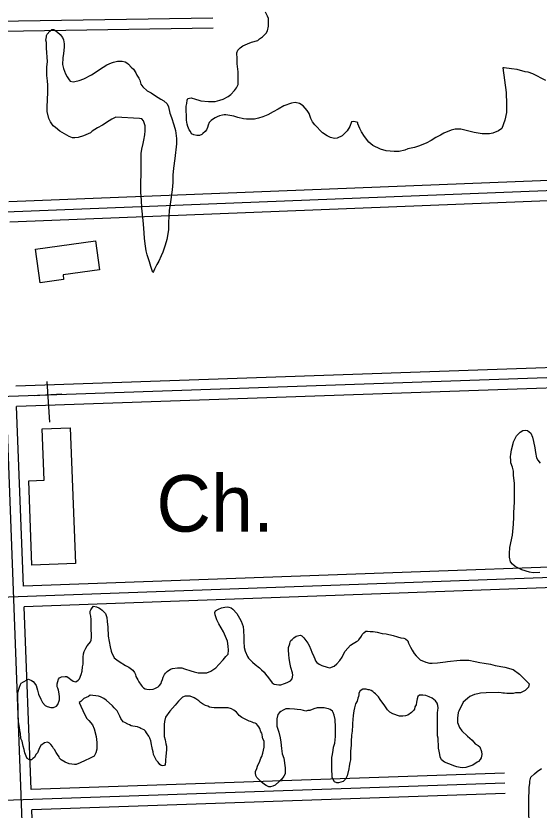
# Model space of a CAD drawing. Extents: x 3313442 to 3351311, y 721974 to 747360.
# Drawn here: x 3329367 to 3330135, y 735697 to 736863 of the extents above; entities that cross this region are included whole.
import ezdxf

# ---------------------------------------------------------------- set-up
doc = ezdxf.new("R2010")
doc.units = 0
for name, color, linetype in [('V-BLDG-OTLN', 7, 'Continuous'), ('V-ROAD-CNTR', 7, 'Continuous'), ('V-SITE-OTLN', 7, 'Continuous'), ('V-SITE-OTLN-IDEN', 7, 'Continuous'), ('V-SITE-VEGE', 7, 'Continuous')]:
    doc.layers.add(name, color=color, linetype=linetype)

msp = doc.modelspace()

# ---------------------------------------------------------------- linework, layer by layer
at = {"layer": 'V-BLDG-OTLN'}
for points in [[(3329395.7, 736520.5), (3329483.8, 736532.8), (3329489.7, 736490.2), (3329436, 736482.7), (3329436.9, 736475.9), (3329402.6, 736471.1)], [(3329390.3, 736056.5), (3329385.6, 736180.3), (3329408.2, 736181.1), (3329405.3, 736256.6), (3329446.7, 736258.2), (3329454.3, 736058.9)]]:
    msp.add_lwpolyline(points, close=True, dxfattribs=at)
at = {"layer": 'V-ROAD-CNTR'}
for points in [[(3329053, 736850.7), (3329656, 736860.3)], [(3329385.8, 735418.9), (3329331.6, 736855.2)], [(3329347.2, 736840.4), (3329656.3, 736845.3)], [(3330731.3, 736644.4), (3329356.6, 736589.9)], [(3330826.8, 736633.2), (3329004.7, 736561)], [(3330827.4, 736618.2), (3329357.7, 736560)], [(3330921, 736373.3), (3329366.8, 736319.4)], [(3330921.6, 736358.4), (3328961.1, 736290.3)], [(3330922.1, 736343.4), (3329367.9, 736289.4)], [(3329377.9, 736025.4), (3329367.9, 736289.4)], [(3331148.5, 736086.5), (3330760.3, 736075.5), (3329377.9, 736025.4)], [(3331148.9, 736071.5), (3330760.7, 736060.5), (3328937.8, 735994.4), (3327458.7, 735955.1), (3325793.6, 735902.5)], [(3330975, 736051.6), (3330761.2, 736045.5), (3329379, 735995.4)], [(3329389.2, 735727.3), (3329379, 735995.4)], [(3330083.8, 735751.3), (3329389.2, 735727.3)], [(3330084.3, 735736.3), (3328967.1, 735697.7)], [(3330084.9, 735721.3), (3329390.3, 735697.3)], [(3329400.2, 735434.5), (3329390.3, 735697.3)]]:
    msp.add_lwpolyline(points, dxfattribs=at)
at = {"layer": 'V-SITE-OTLN'}
for p, q in [((3329416.8, 736266.4), (3329412.9, 736326.3)), ((3329434.1, 736307.6), (3329394.2, 736305.1))]:
    msp.add_line(p, q, dxfattribs=at)
at = {"layer": 'V-SITE-VEGE'}
for points in [[(3329794.3, 736724.1), (3329788.4, 736730.9), (3329783.2, 736734.3), (3329776.6, 736736), (3329771.5, 736734.9), (3329760.1, 736730.7), (3329751.9, 736726.1), (3329744.4, 736722.3), (3329736.8, 736717.7), (3329729.3, 736714.6), (3329723.1, 736712.8), (3329716.9, 736711.4), (3329705.2, 736711.3), (3329700.7, 736711.9), (3329692.7, 736713.9), (3329686.9, 736716), (3329675.1, 736717.6), (3329672.4, 736717.6), (3329670.3, 736717.2), (3329665.5, 736716.1), (3329662.1, 736714.7), (3329659.3, 736713.3), (3329655.2, 736710.9), (3329653.5, 736709.2), (3329650.4, 736706.4), (3329649.1, 736702.6), (3329648.1, 736699.1), (3329646.7, 736695.7), (3329644.7, 736693.2), (3329641.2, 736690.1), (3329639.5, 736688.7), (3329636.4, 736687.6), (3329632.3, 736687.6), (3329628.2, 736688.6), (3329624.7, 736690), (3329623, 736693.1), (3329621.2, 736695.8), (3329619.4, 736700.6), (3329618.4, 736704), (3329617, 736709.9), (3329616.8, 736730.6), (3329617.8, 736734.4), (3329618.1, 736739.5), (3329619.1, 736741.6), (3329624.3, 736742.7), (3329630.2, 736740.7), (3329635.3, 736739.3), (3329638.4, 736738.3), (3329649.5, 736737.4), (3329659.1, 736737.5), (3329666.3, 736739.2), (3329671.2, 736740.7), (3329678.4, 736744.5), (3329682.5, 736747.6), (3329687.6, 736753.5), (3329690.7, 736757.3), (3329693, 736762.5), (3329693.3, 736772.9), (3329693.2, 736780.8), (3329691.8, 736792.5), (3329691.4, 736800.1), (3329691.3, 736809), (3329692.6, 736812.5), (3329696.1, 736816.3), (3329699.8, 736818.8), (3329706.7, 736821.9), (3329712.5, 736824.4), (3329721.8, 736826.9), (3329724.6, 736829.3), (3329729, 736832.1), (3329730.4, 736833.8), (3329734.1, 736837.6), (3329736.2, 736841.1), (3329737.5, 736848), (3329737.4, 736859), (3329736.3, 736862.8), (3329733.2, 736868.7)], [(3329568.8, 736487.9), (3329567.8, 736486.2), (3329564.9, 736494.8), (3329562.8, 736501.7), (3329559.3, 736512), (3329557.8, 736518.2), (3329556.4, 736528.5), (3329555.6, 736536.4), (3329554.8, 736551.2), (3329553.7, 736562.6), (3329551.5, 736580.5), (3329551.1, 736592.2), (3329550.3, 736603.6), (3329550.1, 736621.1), (3329550.8, 736627.7), (3329550.6, 736651.8), (3329550.8, 736661.1), (3329551.8, 736667.3), (3329553.8, 736675.6), (3329554.5, 736680.4), (3329556.1, 736688.4), (3329556.8, 736694.2), (3329556.7, 736701.5), (3329553.9, 736708.7), (3329551.8, 736711.8), (3329548, 736712.4), (3329513.5, 736714.2), (3329507.7, 736711.4), (3329503.6, 736709), (3329494, 736702.4), (3329486.8, 736698.5), (3329478.9, 736693.6), (3329476.2, 736691.5), (3329465.9, 736687), (3329458, 736684.5), (3329453.1, 736684.1), (3329449.7, 736684.1), (3329444.9, 736685.8), (3329431.3, 736693.6), (3329424.8, 736699), (3329421.3, 736701.8), (3329417.8, 736707.3), (3329415.3, 736712.1), (3329412.9, 736722.4), (3329412.8, 736729.6), (3329413.7, 736750.6), (3329413.6, 736761.3), (3329413.2, 736767.5), (3329412.4, 736775.4), (3329412.3, 736787.5), (3329413, 736795.8), (3329411.8, 736815.4), (3329411.7, 736823.7), (3329411, 736827.5), (3329411.6, 736832.3), (3329411.6, 736834.4), (3329412.6, 736836.1), (3329416.7, 736840.6), (3329419.8, 736843), (3329422.6, 736843.1), (3329428.1, 736839.3), (3329431.9, 736835.9), (3329435.4, 736831.1), (3329436.8, 736828), (3329437.9, 736821.8), (3329437.9, 736817), (3329436.6, 736807.7), (3329435.6, 736801.5), (3329435.4, 736791.5), (3329436.5, 736785.6), (3329439.6, 736778.1), (3329442.1, 736773.3), (3329444.9, 736769.2), (3329446.6, 736767.4), (3329450.7, 736766.4), (3329453.2, 736766.5), (3329459.7, 736767.9), (3329466.6, 736770.4), (3329477.9, 736776.3), (3329494.7, 736787.8), (3329500.2, 736791.3), (3329507, 736794.1), (3329510.1, 736795.2), (3329516, 736796.6), (3329522.9, 736796.7), (3329527.4, 736795.3), (3329529.8, 736794), (3329532.2, 736791.9), (3329536, 736787.5), (3329539.2, 736784.7), (3329542.7, 736779.2), (3329544.4, 736775.8), (3329547.2, 736771.7), (3329548.6, 736768.6), (3329550.4, 736762.8), (3329553.2, 736759), (3329559.4, 736753.2), (3329565.3, 736749.8), (3329571.5, 736745.4), (3329575.7, 736743), (3329579.5, 736740.6)], [(3330144.8, 736767.9), (3330125.7, 736778.1), (3330118.8, 736780.4), (3330114.3, 736781.1), (3330102.6, 736784.1), (3330094.3, 736785.4), (3330083.6, 736786.7), (3330081.6, 736786.7), (3330086.3, 736750.5), (3330086.8, 736733.3), (3330086.9, 736721.2), (3330084.6, 736709.9), (3330079.9, 736697.8), (3330075.4, 736694.3), (3330066.8, 736690.8), (3330062, 736690), (3330051.3, 736689.9), (3330039.6, 736691.6), (3330019.9, 736696.9), (3330011.6, 736696.9), (3330005.8, 736695.1), (3329995.1, 736690.9), (3329990, 736687.7), (3329983.1, 736684.2), (3329976.3, 736680), (3329969.1, 736676.2), (3329957.7, 736671.6), (3329951.9, 736669.9), (3329942.3, 736667.7), (3329937.5, 736665.6), (3329929.2, 736663.8), (3329922, 736663.8), (3329910.2, 736665), (3329901.9, 736667.4), (3329890.5, 736672.8), (3329884.6, 736677.6), (3329878.4, 736686.1), (3329874.2, 736693), (3329871.4, 736697.8), (3329868.9, 736704.7), (3329868.9, 736706.7), (3329863, 736708.1), (3329859.2, 736707.4), (3329856.9, 736700.8), (3329852.8, 736694.2), (3329845.6, 736686.9), (3329838.4, 736683.4), (3329834.6, 736683), (3329828.8, 736684.4), (3329823.6, 736686.7), (3329817, 736691.5), (3329805.5, 736702.8), (3329802, 736707.6), (3329799.6, 736712.4), (3329797.1, 736719.6), (3329794.3, 736724.1)], [(3329579.5, 736740.6), (3329584, 736738.2), (3329588.9, 736733.8), (3329590.6, 736729.7), (3329592.8, 736720.4), (3329595.2, 736713.8), (3329598.8, 736702.8), (3329600.9, 736694.9), (3329602.4, 736682.9), (3329602.4, 736675), (3329600.2, 736653.6), (3329598.2, 736639.4), (3329597.3, 736629.1), (3329597, 736618.4), (3329596.1, 736607.7), (3329593.5, 736590.1), (3329591.8, 736577.4), (3329590.6, 736559.8), (3329590.7, 736549.1), (3329588.4, 736534.6), (3329586, 736526.3), (3329582.3, 736515.9), (3329580, 736510.8), (3329576.6, 736502.8), (3329573.5, 736498), (3329570.1, 736491), (3329568.8, 736487.9)], [(3330135.8, 736045.5), (3330126.1, 736045.4), (3330120.9, 736046.1), (3330109.2, 736049.8), (3330099.5, 736054.5), (3330095.7, 736058), (3330092.6, 736061.4), (3330091.1, 736068.3), (3330091.1, 736073.4), (3330091.7, 736082.4), (3330095.7, 736100.3), (3330097.3, 736116.9), (3330097.9, 736126.9), (3330097.8, 736133.4), (3330098.7, 736149.6), (3330098.5, 736176.9), (3330097.4, 736188.2), (3330097.4, 736194.4), (3330095.9, 736200.3), (3330093.5, 736206.8), (3330093.1, 736209.9), (3330093, 736215.8), (3330093.4, 736219.2), (3330094.3, 736225.8), (3330096.7, 736235.1), (3330097, 736237.8), (3330099.4, 736242.7), (3330101.8, 736246.2), (3330106.9, 736251.7), (3330110.7, 736254.2), (3330115.1, 736254.5), (3330117.5, 736254.2), (3330120.3, 736252.5), (3330122.7, 736250.1), (3330125.2, 736244.3), (3330126.3, 736238.1), (3330128.4, 736228.8), (3330129.5, 736221.9), (3330131, 736214.3), (3330133.1, 736210.9), (3330136.2, 736206.1)], [(3329453, 735764), (3329445, 735765), (3329439.1, 735767), (3329433.3, 735770.4), (3329430.8, 735773.1), (3329430.1, 735775.2), (3329428, 735778.6), (3329425.9, 735781.4), (3329423.5, 735785.8), (3329422.1, 735787.5), (3329420.7, 735790.3), (3329418.3, 735793.4), (3329416.2, 735795.1), (3329413.1, 735796.4), (3329408.9, 735795.4), (3329403.5, 735791.5), (3329401.4, 735788.1), (3329400.7, 735786), (3329398.4, 735781.1), (3329396.3, 735778.4), (3329393.9, 735774.2), (3329391.5, 735772.8), (3329389.5, 735770.7), (3329386.7, 735770.4), (3329383.3, 735772.8), (3329381.9, 735775.8), (3329380.1, 735781), (3329379, 735785.8), (3329377.6, 735790.6), (3329375.8, 735798.2), (3329374.1, 735802), (3329373.7, 735809.2), (3329372.6, 735813.7), (3329372.2, 735818.1), (3329370.4, 735826.8), (3329370, 735838.1), (3329369.7, 735869.5), (3329372.1, 735877.4), (3329373.4, 735881.2), (3329374.5, 735883.3), (3329377.9, 735885.4), (3329383.4, 735888.2), (3329385.1, 735889.2), (3329389.9, 735887.2), (3329392.4, 735885.9), (3329395.5, 735881.4), (3329396.5, 735879.7), (3329398.3, 735872.8), (3329400.1, 735867.3), (3329403.6, 735859.8), (3329406, 735855), (3329409.9, 735850.5), (3329412.6, 735849.1), (3329418.2, 735847.5), (3329422, 735847.5), (3329426.4, 735849.3), (3329428.5, 735852), (3329430.8, 735858.9), (3329430.8, 735863.8), (3329429.7, 735870.6), (3329429.3, 735872.7), (3329428.6, 735875.8), (3329427.6, 735877.9), (3329427.5, 735882.3), (3329428.2, 735885.8), (3329429.5, 735889.3), (3329430.9, 735891), (3329434, 735892.7), (3329439.2, 735893.1), (3329441.6, 735892.8), (3329445, 735890.8), (3329447.5, 735888.7), (3329450.9, 735886.3), (3329454.7, 735885.3), (3329458.2, 735887.4), (3329460.2, 735889.8), (3329462.6, 735895.7), (3329463.9, 735900.6), (3329464.6, 735907.1), (3329465.6, 735911.3), (3329465.5, 735921.2), (3329466.1, 735926.1), (3329467.1, 735929.5), (3329469.5, 735934.4), (3329471.5, 735937.8), (3329474.3, 735941.3), (3329476.3, 735943.7), (3329477.3, 735946.5), (3329477.6, 735951), (3329477.5, 735966.1), (3329477.1, 735976.8), (3329476.7, 735981.6), (3329476, 735985.4), (3329476, 735988.9), (3329476.6, 735990.9), (3329479, 735993.7), (3329480.7, 735996.2), (3329484.9, 735995.1), (3329488.7, 735993.8), (3329491.1, 735992.4), (3329493.5, 735990.4)], [(3329493.5, 735990.4), (3329497, 735987), (3329498.4, 735985.3), (3329500.5, 735979.8), (3329500.9, 735973.9), (3329501.6, 735965.3), (3329502.4, 735952.2), (3329505.3, 735936.4), (3329506.8, 735930.2), (3329507.8, 735927.4), (3329510.3, 735923), (3329511.3, 735920.6), (3329515.1, 735917.5), (3329518.6, 735915.1), (3329527.9, 735909.3), (3329532.8, 735906.6), (3329538.7, 735902.2), (3329541.1, 735898.8), (3329542.2, 735896), (3329542.9, 735892.9), (3329545.7, 735888.1), (3329547.1, 735885), (3329550.6, 735880.2), (3329552, 735878.5), (3329554, 735876.5), (3329556.8, 735875.1), (3329558.9, 735874.4), (3329563, 735874.1), (3329568.2, 735874.5), (3329570.9, 735875.6), (3329575.4, 735878), (3329577.1, 735879.4), (3329579.8, 735882.9), (3329580.5, 735885), (3329582.2, 735888.8), (3329582.9, 735891.9), (3329584.9, 735895.7), (3329586.3, 735897.8), (3329588.7, 735900.5), (3329593.8, 735903.7), (3329596.9, 735904.7), (3329603.8, 735905.5), (3329610.3, 735905.5), (3329614.1, 735904.2), (3329623.8, 735901.5), (3329628.3, 735899.8), (3329634.2, 735898.5), (3329638, 735898.2), (3329642.8, 735898.2), (3329646.9, 735898.6), (3329652.8, 735900.7), (3329654.5, 735901.7), (3329660.3, 735905.9), (3329664.7, 735910.4), (3329670.9, 735917.7), (3329675, 735922.2), (3329678.4, 735925.7), (3329678.7, 735931.9), (3329678.6, 735937.4), (3329677.2, 735944.7), (3329675.8, 735948.4), (3329671.6, 735958.4), (3329664.6, 735970.4), (3329661.8, 735976.2), (3329659.3, 735983.5), (3329658.6, 735986.9), (3329659.6, 735989.3), (3329664.1, 735991.8), (3329668.5, 735993.9), (3329673.7, 735994.9), (3329676.8, 735995.3), (3329679.6, 735995), (3329683, 735993.6), (3329685.1, 735991.9), (3329691, 735985.4), (3329694.9, 735978.9), (3329697.3, 735974.1), (3329700.5, 735966.2), (3329700.9, 735960.4), (3329701.3, 735950.7), (3329701.3, 735944.5), (3329702.1, 735935.6), (3329703.2, 735930.4), (3329706.7, 735922.5), (3329708.1, 735920.1), (3329714, 735913.9), (3329717.8, 735910.5)], [(3329717.8, 735910.5), (3329724.4, 735905.8), (3329727.2, 735902.7), (3329731, 735899.3), (3329733.4, 735896.5), (3329737.6, 735891), (3329742.8, 735883.8), (3329746, 735881.8), (3329752.9, 735880.8), (3329755.6, 735880.8), (3329761.1, 735882.6), (3329765.2, 735884.4), (3329769.7, 735886.8), (3329772.1, 735889.6), (3329773.4, 735894.8), (3329773, 735898.6), (3329770.6, 735906.1), (3329769.5, 735911.3), (3329768.1, 735919.2), (3329767.3, 735925.1), (3329766.9, 735931.9), (3329766.9, 735935.7), (3329768.9, 735940.9), (3329769.2, 735944), (3329770.6, 735946.1), (3329772.3, 735947.5), (3329774.7, 735949.9), (3329778.1, 735952), (3329781.9, 735953.4), (3329784.7, 735953.8), (3329786.4, 735952.8), (3329789.5, 735950), (3329795.1, 735941.8), (3329797.2, 735938.4), (3329799.6, 735932.5), (3329801.1, 735928.8), (3329803.9, 735922.2), (3329805.6, 735918.8), (3329806.7, 735916.1), (3329808.4, 735913.7), (3329811.9, 735911.3), (3329815.7, 735909.2), (3329823.6, 735906.6), (3329827.4, 735905.9), (3329834, 735908), (3329838.1, 735911.5), (3329842.5, 735916.7), (3329845.6, 735921.2), (3329848.3, 735926.7), (3329850.3, 735930.2), (3329857.8, 735938.9), (3329861.9, 735941.7), (3329866.7, 735944.5), (3329868.8, 735945.2), (3329870.2, 735946.9), (3329873.9, 735952.1), (3329875.3, 735954.5), (3329877.7, 735957), (3329880.4, 735959.4), (3329882.8, 735959.4), (3329886.6, 735959.1), (3329891.1, 735959.1), (3329893.9, 735958.8), (3329897.3, 735958.1), (3329904.6, 735956.1), (3329910.1, 735955.5), (3329920.8, 735953.2), (3329926.7, 735951.1), (3329931.8, 735949.8), (3329936, 735949.2), (3329938.7, 735948.1), (3329941.9, 735945.4), (3329943.3, 735942), (3329946.1, 735936.1), (3329948.5, 735931.7), (3329951.3, 735926.9), (3329954.1, 735923.5), (3329957.6, 735920), (3329960.4, 735917.6), (3329968.3, 735913.9), (3329973.8, 735912.6), (3329978, 735912.6), (3329985.5, 735913), (3329997.6, 735914.5), (3330000.3, 735915.2), (3330004.5, 735915.6), (3330013.8, 735916.7), (3330018.9, 735917.1), (3330028.2, 735917.2), (3330031.7, 735916.8), (3330041, 735914.8), (3330047.9, 735913.5), (3330054.1, 735912.5), (3330063.4, 735910.9), (3330070.4, 735909.2), (3330084.5, 735906.9), (3330096.9, 735903.2), (3330105.9, 735896.4), (3330111.9, 735890.6), (3330115.7, 735886.5), (3330120.2, 735882.1)], [(3330120.2, 735882.1), (3330119.2, 735877.2), (3330114.4, 735872.4), (3330107.5, 735869.2), (3330105.5, 735868.8), (3330100.3, 735868.8), (3330096.9, 735868.1), (3330087.6, 735868), (3330083.8, 735868.7), (3330081.7, 735868.7), (3330079.3, 735869), (3330075.5, 735869.3), (3330056.9, 735869.1), (3330048.6, 735868.4), (3330044.8, 735867.7), (3330040, 735866.6), (3330033.2, 735863.8), (3330029.7, 735860.7), (3330023.2, 735855.4), (3330016.8, 735842.3), (3330016.1, 735839.9), (3330015.1, 735831.6), (3330015.2, 735825.7), (3330017.7, 735818.2), (3330021.2, 735813.4), (3330029.5, 735805.2), (3330036.4, 735799.4), (3330041, 735794.2), (3330045.4, 735791.9), (3330047.9, 735789.5), (3330050.3, 735782.9), (3330050.7, 735778.5), (3330049.7, 735773.6), (3330048.4, 735771.2), (3330045.6, 735768.4), (3330043.9, 735767.4), (3330037.4, 735762.8), (3330032.9, 735761.1), (3330027.4, 735759.3), (3330022.3, 735758.9), (3330018.8, 735759.3), (3330014, 735760.2), (3330010.9, 735761.3), (3330002.2, 735764.6), (3329995.7, 735767.3), (3329991.5, 735770.7), (3329989.4, 735775.2), (3329989, 735778.7), (3329988.3, 735783.5), (3329987.2, 735787.9), (3329986.9, 735793.8), (3329986.8, 735797.6), (3329986.4, 735802.4), (3329985.7, 735805.9), (3329985.4, 735840), (3329986.1, 735843.1), (3329986.4, 735847.2), (3329986.1, 735850.3), (3329985.3, 735853.7), (3329982.9, 735857.2), (3329977.7, 735861.3), (3329973.5, 735863), (3329968.7, 735865.3), (3329963.9, 735865.6), (3329959, 735865.6), (3329957, 735863.5), (3329955.6, 735860.1), (3329955, 735855.2), (3329954.3, 735851.4), (3329952.6, 735848.3), (3329952, 735845.2), (3329951, 735843.5), (3329947.5, 735840), (3329942.1, 735836.2), (3329938.6, 735835.1), (3329934.8, 735834.7), (3329930, 735834.7), (3329920.3, 735838.4), (3329915.8, 735840.8), (3329912.4, 735843.9), (3329908.5, 735849.7), (3329901.6, 735859.3), (3329899.1, 735863), (3329894.6, 735867.5), (3329892.5, 735868.9), (3329890.8, 735870.9), (3329888.4, 735872.3), (3329885.9, 735873.3), (3329883.9, 735873.6), (3329881.1, 735874.3), (3329875.9, 735874.2), (3329872.2, 735872.1), (3329870.1, 735868.3), (3329870.1, 735866.3), (3329869.8, 735863.5), (3329868.8, 735861.1), (3329867.5, 735856.6), (3329865.4, 735852.8), (3329863.7, 735846.9), (3329862.7, 735842.8), (3329861.8, 735835.5)], [(3329713.7, 735826.1), (3329711.2, 735827.1), (3329709.2, 735827.4), (3329706.4, 735829.1), (3329702.3, 735830.8), (3329698.4, 735832.8), (3329694.6, 735835.6), (3329693.2, 735837.6), (3329690.8, 735840.7), (3329686.6, 735843.4), (3329683.2, 735845.5), (3329678.3, 735846.8), (3329674.6, 735846.8), (3329669, 735847.1), (3329658, 735847), (3329653.9, 735847.6), (3329651.1, 735848), (3329648.3, 735849.3), (3329645.2, 735850.3), (3329640.7, 735852.7), (3329638, 735854.7), (3329635.5, 735857.1), (3329631, 735860.2), (3329628.6, 735861.6), (3329622.4, 735864.3), (3329615.5, 735864.2), (3329611.4, 735862.5), (3329609, 735860.4), (3329605.6, 735856.9), (3329600.4, 735851), (3329592.6, 735842.3), (3329586.4, 735833.3), (3329585.1, 735827.1), (3329584.5, 735822.6), (3329584.6, 735804.7), (3329585.7, 735800.2), (3329586.8, 735794), (3329587.8, 735790.6), (3329587.9, 735785.8), (3329586.9, 735775.4), (3329586.3, 735770.6), (3329586.3, 735768.2), (3329586, 735764), (3329584.9, 735762.3), (3329582.5, 735761.6), (3329580.1, 735762.3), (3329578, 735763.6), (3329575.6, 735767.1), (3329573.2, 735769.8), (3329570.4, 735775.3), (3329569, 735778.7), (3329568.2, 735782.5), (3329567.2, 735785.9), (3329566.5, 735790.8), (3329565.7, 735792.8), (3329565.4, 735796.3), (3329564.7, 735798.7), (3329563.3, 735802.5), (3329561.9, 735805.5), (3329558.7, 735810.3), (3329557, 735812.7), (3329554.9, 735814.5), (3329550.4, 735816.5), (3329548.7, 735817.5), (3329545.2, 735818.9), (3329538.3, 735820.2), (3329535.9, 735820.8), (3329533.5, 735821.9), (3329531, 735823.2), (3329526.9, 735825.3), (3329524.5, 735826.6), (3329521, 735831.4), (3329519.6, 735834.8), (3329515.7, 735842.4), (3329511.2, 735846.8), (3329508.8, 735849.9), (3329499.1, 735858.1), (3329495.9, 735860.5), (3329491.1, 735863.2), (3329488.3, 735864.2), (3329475.9, 735865.5), (3329473.5, 735863.8), (3329470.1, 735862.4), (3329466.3, 735860.6), (3329461.9, 735856.4), (3329459.5, 735854.7), (3329467.5, 735837.9), (3329471, 735831.3), (3329473.8, 735828.6), (3329479.4, 735822.1), (3329481.8, 735816.3), (3329484.7, 735804.9), (3329485.4, 735796.3), (3329485.5, 735786.3), (3329484.2, 735780.8), (3329481.5, 735776), (3329474.9, 735772.5), (3329468.4, 735769.6), (3329461.2, 735766.1), (3329455.4, 735764), (3329453, 735764)], [(3329861.8, 735835.5), (3329860.8, 735823.8), (3329860.8, 735821.4), (3329860.6, 735812.8), (3329859.6, 735806.9), (3329859, 735797.6), (3329859, 735792.1), (3329857.7, 735783.5), (3329857.8, 735770.7), (3329856.8, 735766.9), (3329856.2, 735761.4), (3329855.5, 735757.6), (3329853.2, 735747.2), (3329850.8, 735742.4), (3329847, 735738.9), (3329843.9, 735737.9), (3329840.2, 735736.8), (3329837.7, 735736.8), (3329834.6, 735738.5), (3329832.2, 735742.6), (3329831.1, 735745.3), (3329831.1, 735750.2), (3329830.4, 735753.6), (3329830.3, 735768.1), (3329830.6, 735773.9), (3329831.6, 735778.4), (3329832.5, 735784.6), (3329832.8, 735789.1), (3329834.9, 735795.3), (3329835.8, 735805), (3329836.1, 735809.1), (3329836.1, 735813.6), (3329835.7, 735818.4), (3329835.6, 735830.1), (3329833.8, 735836.3), (3329832.4, 735840.1), (3329831.4, 735842.2), (3329827.9, 735844.6), (3329825.5, 735845.6), (3329823.1, 735845.9), (3329819.3, 735846.9), (3329809, 735846.8), (3329804.1, 735845.7), (3329798.3, 735843.3), (3329795.5, 735842.9), (3329792.4, 735842.2), (3329789, 735842.9), (3329785.2, 735843.9), (3329779.7, 735844.5), (3329775.5, 735845.2), (3329768.6, 735845.5), (3329762.8, 735845.4), (3329759, 735843.7), (3329755.6, 735841.6), (3329753.5, 735840.2), (3329751.1, 735837), (3329749.8, 735830.8), (3329749.9, 735820.2), (3329752.7, 735811.2), (3329754.9, 735803), (3329755.9, 735796.8), (3329756.7, 735787.1), (3329757.8, 735779.6), (3329759.9, 735773), (3329762.1, 735758.9), (3329762.2, 735750), (3329760.1, 735746.5), (3329756.7, 735741.6), (3329753.3, 735738.9), (3329747.5, 735733.6), (3329744.1, 735732.2), (3329740.3, 735731.2), (3329737.9, 735731.1), (3329734.1, 735732.8), (3329731.6, 735734.2), (3329726.4, 735738.6), (3329723.6, 735741.7), (3329720.5, 735744.8), (3329719.1, 735747.5), (3329718.7, 735751), (3329718.7, 735753.4), (3329720.4, 735757.9), (3329721.4, 735761.3), (3329724.8, 735768.6), (3329726.1, 735773.1), (3329727.9, 735775.5), (3329729.5, 735780.4), (3329731.2, 735789.3), (3329731.1, 735797.9), (3329729.4, 735801.7), (3329729, 735804.1), (3329728.3, 735807.6), (3329727.6, 735809.6), (3329726.5, 735812), (3329725.1, 735816.5), (3329723.4, 735818.9), (3329721.6, 735821.6), (3329719.9, 735823.4), (3329718.2, 735824.7), (3329715.7, 735825), (3329713.7, 735826.1)], [(3330135.6, 735637.5), (3330132.2, 735636.4), (3330126.3, 735637.4), (3330124.5, 735640.5), (3330122.8, 735647.7), (3330121.7, 735653.6), (3330120.9, 735665.7), (3330120.8, 735678.4), (3330120.1, 735684.3), (3330119.7, 735688.7), (3330119.6, 735700.4), (3330119.9, 735709.1), (3330119.8, 735715.3), (3330120.4, 735724.6), (3330120.4, 735730.1), (3330121, 735736.3), (3330121, 735739.4), (3330122, 735743.2), (3330122.7, 735745.3), (3330127.8, 735750.1), (3330131.9, 735753.6), (3330138.1, 735758.1)]]:
    msp.add_lwpolyline(points, dxfattribs=at)

# ---------------------------------------------------------------- texts
at = {"layer": 'V-SITE-OTLN-IDEN'}
msp.add_text('Ch.', height=83, dxfattribs=at).set_placement((3329573, 736105.7))

doc.saveas('drawing.dxf')
